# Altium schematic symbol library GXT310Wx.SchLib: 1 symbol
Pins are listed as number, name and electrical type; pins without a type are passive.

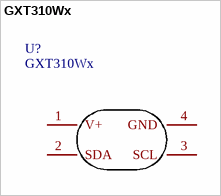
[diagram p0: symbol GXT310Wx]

## GXT310Wx
designator U?
footprint WLCSP-4-0.73*0.73mm-P0.4mm
pins: 1 V+, 2 SDA, 3 SCL, 4 GND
